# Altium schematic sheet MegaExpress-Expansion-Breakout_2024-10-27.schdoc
size 155 x 170 mm
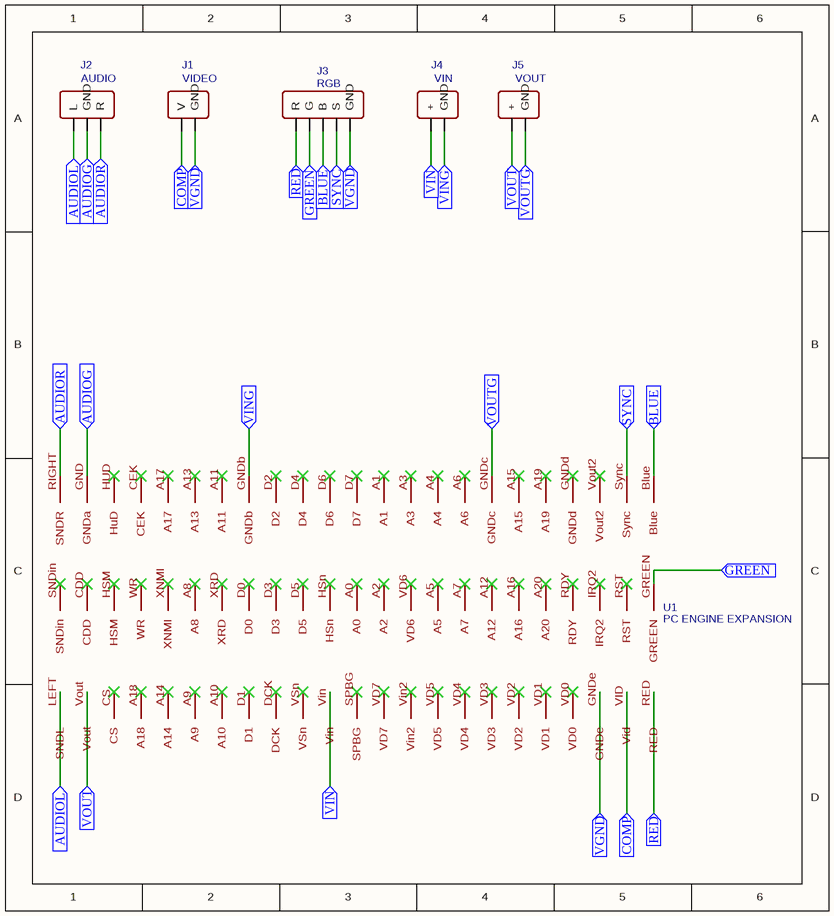
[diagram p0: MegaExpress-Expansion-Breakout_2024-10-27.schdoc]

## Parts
J1  VIDEO  [HDR-M-2.54_1X2]
J2  AUDIO  [HDR-M-2.54_1X3]
J3  RGB  [HDR-M-2.54_1X5]
J4  VIN  [HDR-M-2.54_1X2]
J5  VOUT  [HDR-M-2.54_1X2]
U1  PC ENGINE EXPANSION  [PC ENGINE EXPANSION]

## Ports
AUDIOG (in), AUDIOL (in), AUDIOR (in), BLUE (in), COMP (in), GREEN (in), RED (in), SYNC (in), VGND (in), VIN (in), VING (in), VOUT (in), VOUTG (in)

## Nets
AUDIOG: J2.2(GND) U1.GND(GNDa) ; port AUDIOG
AUDIOL: J2.1(L) U1.LEFT(SNDL) ; port AUDIOL
AUDIOR: J2.3(R) U1.RIGHT(SNDR) ; port AUDIOR
BLUE: J3.3(B) U1.Blue ; port BLUE
COMP: J1.1(V) U1.VID(Vid) ; port COMP
GREEN: J3.2(G) U1.GREEN ; port GREEN
RED: J3.1(R) U1.RED ; port RED
SYNC: J3.4(S) U1.Sync ; port SYNC
VGND: J1.2(GND) J3.5(GND) U1.GNDe ; port VGND
VIN: J4.1(+) U1.Vin ; port VIN
VING: J4.2(GND) U1.GNDb ; port VING
VOUT: J5.1(+) U1.Vout ; port VOUT
VOUTG: J5.2(GND) U1.GNDc ; port VOUTG

Not connected (* = marked no-connect by the designer): U1 A0* A1* A2* A3* A4* A5* A6* A7* A8* A9* A10* A11* A12* A13* A14* A15* A16* A17* A18* A19* A20* CDD* CEK* CS* D0* D1* D2* D3* D4* D5* D6* D7* DCK* GNDd* HSM* HSn* HUD(HuD)* IRQ2* RDY* RST* SNDin* SPBG* VD0* VD1* VD2* VD3* VD4* VD5* VD6* VD7* Vin2* Vout2* VSn* WR* XNMI* XRD*

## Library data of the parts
J1 = VIDEO: Contributor: LCEDA_Lib
J2 = AUDIO: Contributor: LCEDA_Lib
J3 = RGB: Contributor: LCEDA_Lib
J4 = VIN: Contributor: LCEDA_Lib
J5 = VOUT: Contributor: LCEDA_Lib
U1 = PC ENGINE EXPANSION: Contributor: jonn.blanchard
